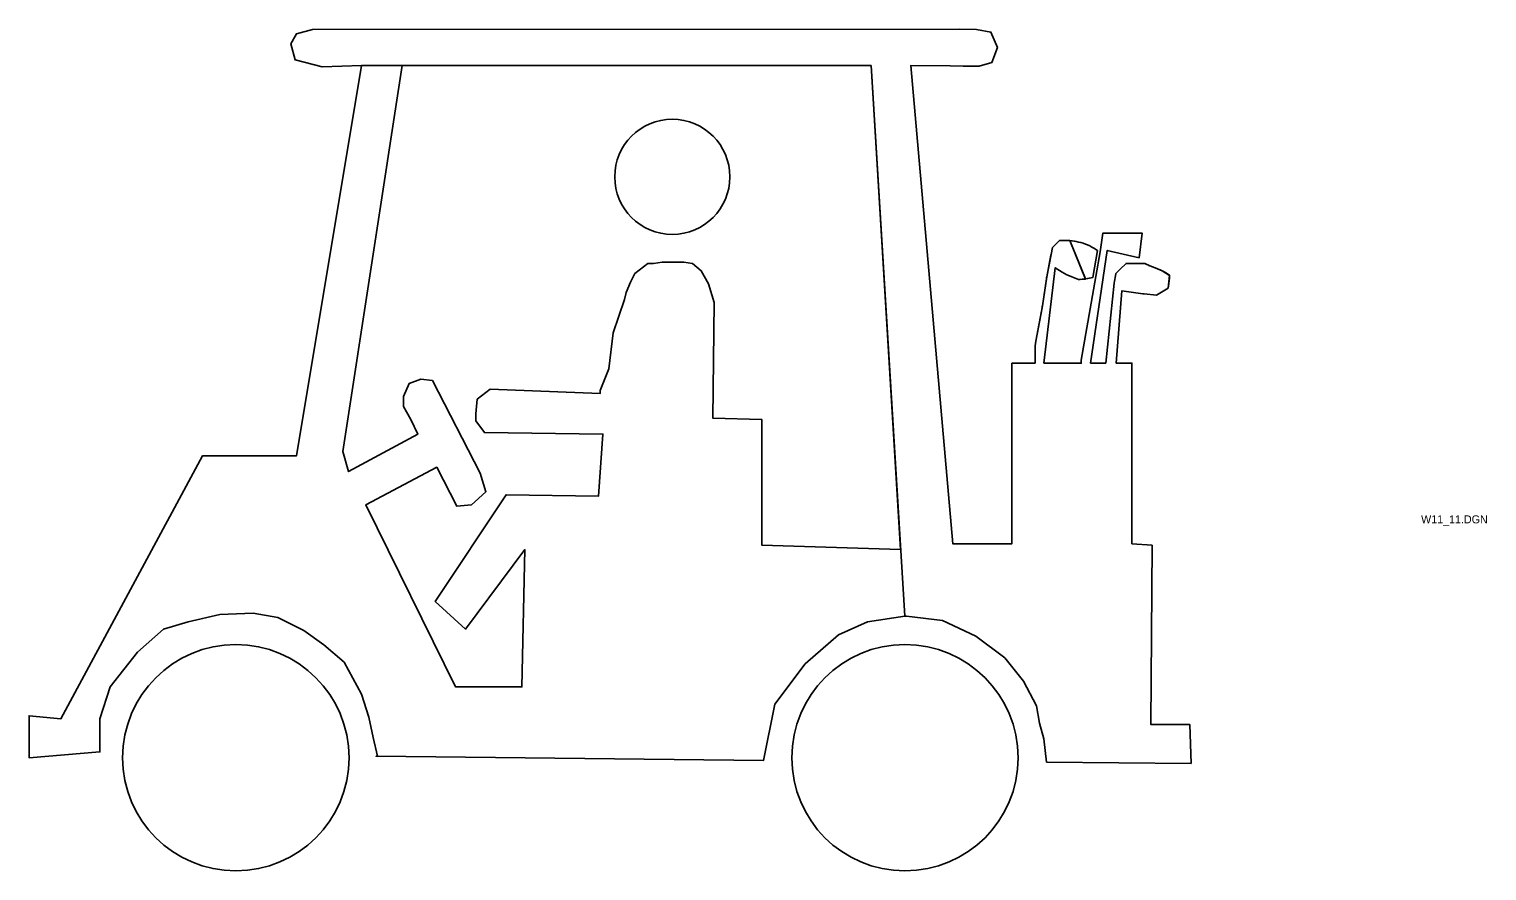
# Model space of a CAD drawing. Extents: x -0.249 to 0.289, y -0.061 to 0.281.
# Drawn here: x -0.2486 to 0.0247, y -0.0608 to 0.097 of the extents above; entities that cross this region are included whole.
import ezdxf

# ---------------------------------------------------------------- set-up
doc = ezdxf.new("R2010")
doc.units = 0
doc.layers.add('1', color=7, linetype='Continuous')

msp = doc.modelspace()

# ---------------------------------------------------------------- linework, layer by layer
at = {"layer": '1'}
for p, q in [((-0.18625068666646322, 0.09020722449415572), (-0.09075620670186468, 0.09021868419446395)), ((-0.09075620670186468, 0.09021868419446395), (-0.09072975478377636, 0.09021807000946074)), ((-0.08442831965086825, -0.013057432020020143), (-0.09072975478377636, 0.09021807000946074)), ((-0.09072975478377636, 0.09021807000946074), (-0.08442831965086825, -0.013057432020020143)), ((-0.052305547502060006, 0.05721657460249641), (-0.05349258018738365, 0.05743240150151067)), ((-0.05349258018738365, 0.05743240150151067), (-0.05052013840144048, 0.05019742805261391)), ((-0.05051633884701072, 0.05018983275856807), (-0.05349258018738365, 0.05743240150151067)), ((-0.057002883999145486, 0.054782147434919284), (-0.057793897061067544, 0.050567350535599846)), ((-0.05702579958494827, 0.05466387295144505), (-0.057793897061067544, 0.050567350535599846)), ((-0.052305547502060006, 0.05721657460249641), (-0.05260542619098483, 0.05727109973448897)), ((-0.049157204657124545, 0.05049058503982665), (-0.048265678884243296, 0.05554255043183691)), ((-0.048265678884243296, 0.05554255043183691), (-0.04894944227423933, 0.055952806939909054)), ((-0.048265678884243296, 0.05554255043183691), (-0.04894944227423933, 0.055952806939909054)), ((-0.04780300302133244, 0.055264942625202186), (-0.04861579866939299, 0.050659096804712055)), ((-0.057793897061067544, 0.050567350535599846), (-0.05861490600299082, 0.045138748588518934)), ((-0.05785454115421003, 0.05020786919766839), (-0.05861490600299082, 0.045138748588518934)), ((-0.05052013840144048, 0.05019742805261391), (-0.0518641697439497, 0.05011723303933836)), ((-0.05861490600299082, 0.045138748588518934), (-0.05982923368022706, 0.03855309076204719)), ((-0.058671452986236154, 0.044801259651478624), (-0.05982783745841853, 0.038556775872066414)), ((-0.059995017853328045, 0.03674046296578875), (-0.059995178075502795, 0.03440316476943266)), ((-0.059995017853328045, 0.03673658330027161), (-0.059995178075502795, 0.03440316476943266))]:
    msp.add_line(p, q, dxfattribs=at)
for points in [[(-0.059995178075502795, 0.03440316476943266), (-0.06378800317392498, 0.03440316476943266), (-0.06432986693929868, 0.03440316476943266), (-0.06432986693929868, 0.0005366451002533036), (-0.07543808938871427, 0.0005366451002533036), (-0.08329512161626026, 0.09021519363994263), (-0.07592294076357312, 0.09013905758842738), (-0.07345989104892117, 0.09009506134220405), (-0.07046904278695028, 0.09009506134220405), (-0.06812292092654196, 0.09075705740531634), (-0.06703836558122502, 0.09357077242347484), (-0.06827974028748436, 0.09649255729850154), (-0.07095285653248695, 0.09695849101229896), (-0.07414529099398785, 0.09703576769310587), (-0.19546105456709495, 0.09698849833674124), (-0.19844130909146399, 0.09617570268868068), (-0.19952503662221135, 0.09427917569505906), (-0.19871224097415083, 0.09129892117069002), (-0.19364430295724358, 0.08999081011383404), (-0.18625068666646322, 0.09020722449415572)], [(-0.186249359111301, 0.09021519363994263), (-0.19844130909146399, 0.017063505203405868), (-0.21605190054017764, 0.017063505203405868), (-0.24260325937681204, -0.03224615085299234), (-0.2485637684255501, -0.031704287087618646), (-0.2485637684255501, -0.03956131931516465), (-0.23528808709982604, -0.03847759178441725), (-0.23528808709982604, -0.03224615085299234), (-0.23339156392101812, -0.02628564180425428), (-0.22824385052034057, -0.01978326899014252), (-0.22336707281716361, -0.015448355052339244), (-0.2187612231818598, -0.014093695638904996), (-0.21280071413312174, -0.012739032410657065), (-0.20656927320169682, -0.012468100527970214), (-0.2019634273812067, -0.013280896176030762), (-0.19708664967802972, -0.015719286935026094), (-0.19329359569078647, -0.018428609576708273), (-0.18950054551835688, -0.02167979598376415), (-0.186249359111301, -0.027640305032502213), (-0.18489469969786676, -0.03197521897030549), (-0.1840819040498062, -0.03576826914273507), (-0.183269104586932, -0.0392903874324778), (-0.18354003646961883, -0.0392903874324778), (-0.11093020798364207, -0.04010318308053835), (-0.1087627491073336, -0.029536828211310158), (-0.10307317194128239, -0.021950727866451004), (-0.09684173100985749, -0.01653208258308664), (-0.0914230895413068, -0.014093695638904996), (-0.08442831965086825, -0.013057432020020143)], [(-0.09072975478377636, 0.09021807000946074), (-0.0851916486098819, -0.0005470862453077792), (-0.11120113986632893, 0.00026570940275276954), (-0.11120113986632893, 0.023836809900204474), (-0.12041283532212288, 0.024107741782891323), (-0.12014190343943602, 0.0457823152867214), (-0.12122563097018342, 0.04930443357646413), (-0.12258029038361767, 0.05174282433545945), (-0.12420588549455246, 0.05309748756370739), (-0.12583147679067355, 0.053368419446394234), (-0.12772800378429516, 0.053368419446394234), (-0.12989546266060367, 0.053368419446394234), (-0.13152105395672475, 0.05309748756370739), (-0.13260478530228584, 0.05309748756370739), (-0.1350431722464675, 0.05120096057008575), (-0.13585597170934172, 0.049575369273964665), (-0.13666876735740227, 0.047678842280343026), (-0.1369396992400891, 0.04632418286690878), (-0.1391071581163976, 0.04009274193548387), (-0.13991995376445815, 0.03331943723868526), (-0.14154554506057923, 0.029255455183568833), (-0.14154554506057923, 0.02871359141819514), (-0.16213639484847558, 0.029526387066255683), (-0.16457478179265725, 0.027629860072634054), (-0.16484571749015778, 0.02492053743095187), (-0.16484571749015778, 0.023565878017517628), (-0.163220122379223, 0.021398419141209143), (-0.14100368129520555, 0.021127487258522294), (-0.14181647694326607, 0.00947740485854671), (-0.15915614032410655, 0.009748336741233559), (-0.17243181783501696, -0.010300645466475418), (-0.16674224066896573, -0.015448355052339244), (-0.15563402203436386, -0.0005470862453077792), (-0.15617588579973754, -0.02628564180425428), (-0.16863876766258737, -0.02628564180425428), (-0.18543656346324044, 0.00785181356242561), (-0.1721608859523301, 0.014896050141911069), (-0.1683678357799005, 0.007580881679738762), (-0.16565851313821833, 0.00785181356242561), (-0.16294919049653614, 0.010290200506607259), (-0.16403291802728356, 0.013812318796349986), (-0.17297368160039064, 0.03115197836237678), (-0.17514114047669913, 0.03142291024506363), (-0.17730859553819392, 0.030610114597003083), (-0.178392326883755, 0.028171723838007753), (-0.178392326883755, 0.026275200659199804), (-0.17703766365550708, 0.023836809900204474), (-0.17568300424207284, 0.021127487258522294), (-0.18868774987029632, 0.014083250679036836), (-0.18977147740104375, 0.017876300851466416), (-0.17866325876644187, 0.09021519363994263)], [(-0.17866322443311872, 0.09021541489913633), (-0.09072975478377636, 0.09021807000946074)], [(-0.05439428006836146, 0.05743240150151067), (-0.05538910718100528, 0.05743240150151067), (-0.056743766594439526, 0.056077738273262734), (-0.057002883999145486, 0.054782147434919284)], [(-0.05349258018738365, 0.05743240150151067), (-0.05538910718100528, 0.05743240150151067), (-0.056743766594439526, 0.056077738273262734), (-0.057002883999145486, 0.054782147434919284)], [(-0.045167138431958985, 0.049419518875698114), (-0.04674710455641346, 0.034412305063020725), (-0.04958259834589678, 0.034412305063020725), (-0.046448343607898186, 0.055535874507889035), (-0.04048783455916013, 0.05418121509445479), (-0.03994597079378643, 0.05878706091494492), (-0.04726113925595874, 0.05878706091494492), (-0.04780300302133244, 0.055264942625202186)], [(-0.045167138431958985, 0.049419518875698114), (-0.04674710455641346, 0.034412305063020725), (-0.04958259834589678, 0.034412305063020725), (-0.046448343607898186, 0.055535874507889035), (-0.04048783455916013, 0.05418121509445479), (-0.03994597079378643, 0.05878706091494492), (-0.04726113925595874, 0.05878706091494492), (-0.04780300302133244, 0.055264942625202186)], [(-0.058361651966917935, 0.03440316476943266), (-0.05620190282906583, 0.05228468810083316), (-0.05488454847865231, 0.05146134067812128)], [(-0.058361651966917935, 0.03440316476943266), (-0.05620190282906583, 0.05228468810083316), (-0.05488454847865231, 0.05146134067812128)], [(-0.039234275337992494, 0.05301256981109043), (-0.03940410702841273, 0.05309748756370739), (-0.04075876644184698, 0.05309748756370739), (-0.042655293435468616, 0.05309748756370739), (-0.04292622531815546, 0.05309748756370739), (-0.04400995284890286, 0.05201375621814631), (-0.04482274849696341, 0.05120096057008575), (-0.044923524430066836, 0.050797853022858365)], [(-0.038476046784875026, 0.052672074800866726), (-0.03940410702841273, 0.05309748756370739), (-0.04075876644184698, 0.05309748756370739), (-0.042655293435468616, 0.05309748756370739), (-0.04292622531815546, 0.05309748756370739), (-0.04400995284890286, 0.05201375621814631), (-0.04482274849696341, 0.05120096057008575), (-0.044923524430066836, 0.050797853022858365)], [(-0.03689688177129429, 0.052040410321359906), (-0.037507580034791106, 0.05228468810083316), (-0.038476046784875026, 0.052672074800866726)], [(-0.03615292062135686, 0.05174282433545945), (-0.037507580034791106, 0.05228468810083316), (-0.038476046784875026, 0.052672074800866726)], [(-0.04861579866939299, 0.050659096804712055), (-0.05132512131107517, 0.03494502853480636), (-0.05132512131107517, 0.03440316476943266), (-0.058361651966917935, 0.03440316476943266)], [(-0.05309579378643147, 0.05057803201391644), (-0.051866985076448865, 0.05011723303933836), (-0.0518641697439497, 0.05011723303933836)], [(-0.05309579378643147, 0.05057803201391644), (-0.051866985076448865, 0.05011723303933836), (-0.05051633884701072, 0.05018983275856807)], [(-0.03956623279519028, 0.04739582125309), (-0.03723664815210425, 0.04713697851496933), (-0.035069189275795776, 0.04849163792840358), (-0.03479825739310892, 0.050836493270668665), (-0.03615292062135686, 0.05174282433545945)], [(-0.03479825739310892, 0.050836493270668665), (-0.03479825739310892, 0.05093002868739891), (-0.03546583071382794, 0.05133057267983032)], [(-0.030734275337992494, -0.04064504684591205), (-0.031005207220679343, -0.03332987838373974), (-0.03832037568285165, -0.03332987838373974), (-0.038049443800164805, 0.00026570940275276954), (-0.041842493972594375, 0.0005366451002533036), (-0.04184125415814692, 0.034412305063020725), (-0.04481176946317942, 0.034412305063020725), (-0.04373902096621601, 0.04794977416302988), (-0.039783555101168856, 0.04742237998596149)], [(-0.030734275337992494, -0.04064504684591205), (-0.031005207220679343, -0.03332987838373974), (-0.03832037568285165, -0.03332987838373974), (-0.038049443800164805, 0.00026570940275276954), (-0.041842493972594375, 0.0005366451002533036), (-0.04184125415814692, 0.034412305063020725), (-0.04481176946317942, 0.034412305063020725), (-0.04373902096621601, 0.04794977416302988), (-0.039783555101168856, 0.04742237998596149)], [(-0.03956623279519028, 0.04739582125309), (-0.03723664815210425, 0.04713697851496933), (-0.035069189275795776, 0.04849163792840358), (-0.03499245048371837, 0.048875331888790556)], [(-0.08442831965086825, -0.013057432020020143), (-0.0841079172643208, -0.013009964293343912), (-0.0773346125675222, -0.013822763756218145), (-0.07110317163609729, -0.01680301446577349), (-0.0656845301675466, -0.020867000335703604), (-0.06216241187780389, -0.025201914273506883), (-0.05972402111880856, -0.029807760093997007), (-0.059182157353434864, -0.033058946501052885), (-0.05836936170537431, -0.03603920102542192), (-0.05782749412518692, -0.0403741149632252), (-0.030734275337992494, -0.04064504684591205)]]:
    msp.add_lwpolyline(points, dxfattribs=at)
for centre, radius in [((-0.12799893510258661, 0.06935342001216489), 0.01079657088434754), ((-0.20982046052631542, -0.039561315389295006), 0.021217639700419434), ((-0.0843788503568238, -0.039561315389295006), 0.021217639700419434)]:
    msp.add_circle(centre, radius, dxfattribs=at)
for centre, radius, start, end in [((-0.05439427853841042, 0.04743240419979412), 0.01, 79.69515449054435, 89.99999982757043), ((-0.04719707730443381, 0.052820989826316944), 0.010000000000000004, 168.69006589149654, 169.3803437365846), ((-0.05409439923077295, 0.047377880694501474), 0.010000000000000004, 59.03624518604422, 79.69515449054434), ((-0.054094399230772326, 0.047377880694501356), 0.010000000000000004, 59.03624518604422, 79.69515449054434), ((-0.03476213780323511, 0.061956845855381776), 0.009999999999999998, 243.43495100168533, 248.1985927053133), ((-0.04061078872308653, 0.042755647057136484), 0.010000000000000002, 59.03624579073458, 68.1985920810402), ((-0.04796517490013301, 0.048724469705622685), 0.010000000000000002, 169.3803437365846, 171.4692335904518), ((-0.04958455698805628, 0.0599413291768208), 0.010000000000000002, 237.99461942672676, 249.4439564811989), ((-0.04958455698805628, 0.0599413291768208), 0.010000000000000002, 237.99461942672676, 249.4439564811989), ((-0.05186416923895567, 0.060117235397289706), 0.01, 270.00000014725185, 285.70572703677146), ((-0.05186416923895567, 0.060117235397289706), 0.010000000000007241, 270.00000019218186, 285.70572703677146), ((-0.03522210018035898, 0.048372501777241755), 0.010000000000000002, 165.96375439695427, 173.99000464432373), ((-0.03522210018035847, 0.04837250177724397), 0.010000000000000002, 165.96375439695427, 173.99000464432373), ((-0.04479825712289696, 0.05083649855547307), 0.01, 348.6900660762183, 359.9999992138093), ((-0.038461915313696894, 0.05733466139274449), 0.010000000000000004, 262.4053574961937, 263.6598087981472), ((-0.03846191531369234, 0.05733466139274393), 0.010000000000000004, 262.4053574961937, 263.6598087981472), ((-0.06850427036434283, 0.046622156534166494), 0.01, 349.5085220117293, 351.46923359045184), ((-0.04999501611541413, 0.03673588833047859), 0.01, 169.5085220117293, 179.99600206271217), ((-0.049995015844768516, 0.03673976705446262), 0.01, 169.5525992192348, 179.99600206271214)]:
    msp.add_arc(centre, radius, start, end, dxfattribs=at)

# ---------------------------------------------------------------- texts
msp.add_text('W11_11.DGN', height=0.0015, dxfattribs=at).set_placement((0.012375, 0.004375))

doc.saveas('drawing.dxf')
